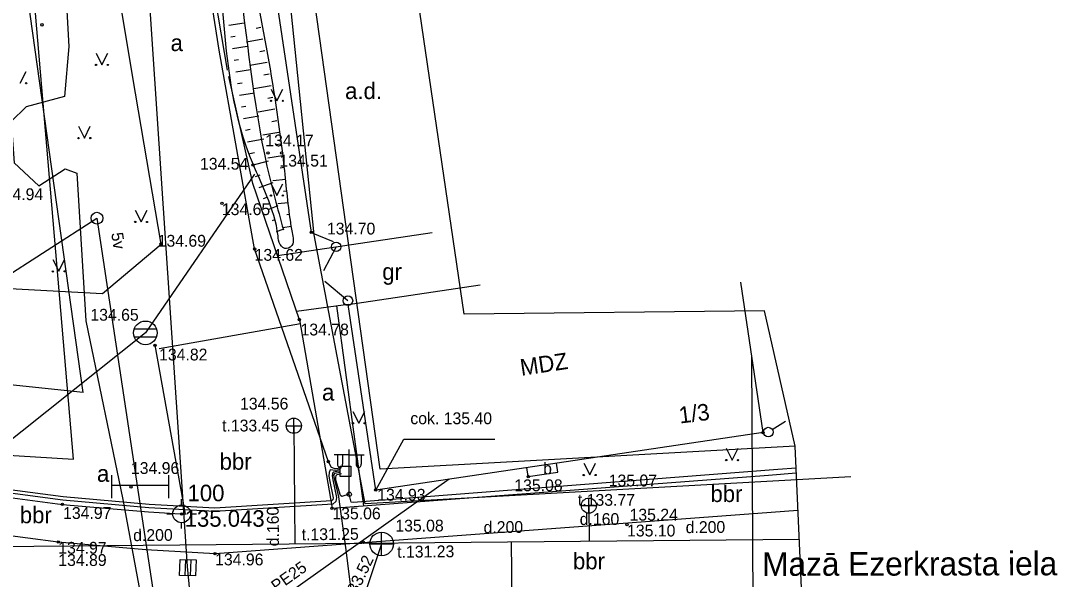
# Model space of a CAD drawing. Extents: x 728710 to 728960, y 272811 to 273475.
# Drawn here: x 728772.47 to 728816.33, y 273368.37 to 273391.98 of the extents above; entities that cross this region are included whole.
import ezdxf

# ---------------------------------------------------------------- set-up
doc = ezdxf.new("R2010")
doc.units = 0
for name, color, linetype in [('Level 10', 7, 'Continuous'), ('Level 12', 7, 'Continuous'), ('Level 15', 7, 'Continuous'), ('Level 17', 7, 'Continuous'), ('Level 18', 7, 'Continuous'), ('Level 19', 7, 'Continuous'), ('Level 21', 7, 'Continuous'), ('Level 23', 7, 'Continuous'), ('Level 25', 7, 'Continuous'), ('Level 26', 7, 'Continuous'), ('Level 28', 7, 'Continuous'), ('Level 29', 7, 'Continuous'), ('Level 3', 7, 'Continuous'), ('Level 34', 7, 'Continuous'), ('Level 38', 7, 'Continuous'), ('Level 4', 7, 'Continuous'), ('Level 40', 7, 'Continuous'), ('Level 42', 7, 'Continuous'), ('Level 43', 7, 'Continuous'), ('Level 48', 7, 'Continuous'), ('Level 50', 7, 'Continuous'), ('Level 53', 7, 'Continuous'), ('Level 54', 7, 'Continuous'), ('Level 55', 7, 'Continuous'), ('Level 56', 7, 'Continuous'), ('Level 57', 7, 'Continuous'), ('Level 58', 7, 'Continuous'), ('Level 59', 7, 'Continuous'), ('Level 60', 7, 'Continuous'), ('Level 62', 7, 'Continuous'), ('Level 63', 7, 'Continuous'), ('Level 9', 7, 'Continuous'), ('RAMI_UZMR_####_####_#', 7, 'Continuous'), ('ROBZ_ELEM_####_####_#', 7, 'Continuous'), ('ROBZ_PROJ_####_####_#', 7, 'Continuous'), ('ROBZ_UZMR_####_####_#', 7, 'Continuous'), ('TERT_KOKR_####_####_#', 7, 'Continuous'), ('TERT_KONT_####_####_#', 7, 'Continuous')]:
    doc.layers.add(name, color=color, linetype=linetype)

msp = doc.modelspace()

# ---------------------------------------------------------------- linework, layer by layer
at = {"layer": 'Level 10'}
for p, q in [((728779.278, 273371.512), (728779.278, 273371.762)), ((728778.653, 273371.137), (728778.903, 273371.137)), ((728779.278, 273370.512), (728779.278, 273370.762)), ((728779.653, 273371.137), (728779.903, 273371.137))]:
    msp.add_line(p, q, dxfattribs=at)
for radius in [0.375, 0.05]:
    msp.add_circle((728779.278, 273371.137), radius, dxfattribs=at)
at = {"layer": 'Level 12'}
for p, q in [((728781.28, 273391.804), (728781.919, 273391.896)), ((728782.634, 273391.693), (728782.432, 273391.658)), ((728781.352, 273391.309), (728781.541, 273391.337)), ((728782.719, 273391.2), (728782.027, 273391.081)), ((728781.424, 273390.814), (728782.051, 273390.906)), ((728782.804, 273390.708), (728782.592, 273390.671)), ((728781.497, 273390.32), (728781.684, 273390.348)), ((728782.89, 273390.215), (728782.169, 273390.09)), ((728781.571, 273389.825), (728782.195, 273389.92)), ((728782.975, 273389.722), (728782.756, 273389.685)), ((728781.647, 273389.331), (728781.835, 273389.36)), ((728783.059, 273389.229), (728782.327, 273389.105)), ((728781.725, 273388.837), (728782.357, 273388.938)), ((728783.142, 273388.736), (728782.924, 273388.7)), ((728781.806, 273388.344), (728781.998, 273388.375)), ((728781.889, 273387.851), (728782.543, 273387.962)), ((728783.225, 273388.243), (728782.51, 273388.124)), ((728783.306, 273387.75), (728783.098, 273387.716)), ((728781.974, 273387.358), (728782.176, 273387.394)), ((728782.064, 273386.866), (728782.749, 273386.994)), ((728783.386, 273387.256), (728782.716, 273387.148)), ((728783.465, 273386.762), (728783.272, 273386.732)), ((728782.157, 273386.375), (728782.366, 273386.415)), ((728783.542, 273386.268), (728782.927, 273386.174)), ((728782.261, 273385.886), (728782.952, 273386.062)), ((728783.616, 273385.774), (728783.441, 273385.75)), ((728782.399, 273385.405), (728782.594, 273385.468)), ((728783.679, 273385.278), (728783.136, 273385.214)), ((728782.563, 273384.933), (728783.15, 273385.152)), ((728783.734, 273384.781), (728783.586, 273384.766)), ((728782.744, 273384.467), (728782.897, 273384.528)), ((728782.932, 273384.004), (728783.36, 273384.177)), ((728783.785, 273384.284), (728783.347, 273384.238)), ((728783.118, 273383.54), (728783.223, 273383.58)), ((728783.84, 273383.787), (728783.724, 273383.773)), ((728783.293, 273383.071), (728783.575, 273383.17)), ((728783.905, 273383.291), (728783.562, 273383.233)), ((728783.416, 273382.588), (728783.416, 273382.588)), ((728783.994, 273382.799), (728783.994, 273382.799)), ((728783.807, 273382.38), (728783.807, 273382.381))]:
    msp.add_line(p, q, dxfattribs=at)
msp.add_spline([(728781.578, 273417.978), (728780.943, 273413.169), (728780.822, 273403.542), (728781.949, 273395.724), (728783.589, 273385.96), (728783.878, 273383.473), (728783.979, 273382.874), (728783.979, 273382.553), (728783.717, 273382.35), (728783.447, 273382.528), (728783.355, 273382.891), (728782.193, 273386.189), (728780.645, 273395.989), (728779.246, 273403.69), (728779.989, 273412.965), (728780.695, 273417.894)], degree=3, dxfattribs=at)
at = {"layer": 'Level 15'}
msp.add_circle((728775.694, 273383.637), 0.25, dxfattribs=at)
at = {"layer": 'Level 17'}
msp.add_line((728790.602, 273372.604), (728781.127, 273365.888), dxfattribs=at)
at = {"layer": 'Level 18'}
for p, q in [((728782.361, 273385.497), (728777.745, 273378.79)), ((728777.745, 273378.79), (728760.582, 273365.124))]:
    msp.add_line(p, q, dxfattribs=at)
for points in [[(728779.523, 273368.911), (728776.197, 273418.56)], [(728780.99, 273353.695), (728779.523, 273368.911)]]:
    msp.add_lwpolyline(points, dxfattribs=at)
at = {"layer": 'Level 21'}
for p, q in [((728763.288, 273375.684), (728775.694, 273383.637)), ((728775.694, 273383.637), (728780.859, 273349.374))]:
    msp.add_line(p, q, dxfattribs=at)
at = {"layer": 'Level 23'}
for p, q in [((728784.022, 273374.863), (728784.068, 273369.87)), ((728796.509, 273371.486), (728796.523, 273369.985)), ((728767.599, 273369.717), (728805.41, 273370.068)), ((728787.739, 273369.866), (728785.477, 273363.156)), ((728793.293, 273364.348), (728793.241, 273369.955))]:
    msp.add_line(p, q, dxfattribs=at)
at = {"layer": 'Level 25'}
for points in [[(728786.021, 273373.071), (728785.768, 273373.044), (728785.616, 273373.092), (728785.488, 273373.338), (728782.365, 273382.337), (728780.872, 273390.743), (728779.255, 273401.013)], [(728786.002, 273373.007), (728785.781, 273372.977), (728785.555, 273373), (728785.522, 273372.892), (728785.51, 273372.736), (728785.536, 273372.57), (728785.684, 273371.822), (728785.672, 273371.733), (728785.619, 273371.691), (728780.679, 273371.377), (728777.898, 273371.536), (728774.268, 273371.854), (728756.308, 273374.215), (728748.126, 273375.149), (728746.387, 273375.649), (728746.387, 273375.794), (728746.374, 273376.209), (728746.26, 273375.684), (728746.005, 273375.707)], [(728785.99, 273372.939), (728785.838, 273372.922), (728785.697, 273372.9), (728785.665, 273372.858), (728785.649, 273372.748), (728785.68, 273372.573), (728785.827, 273371.826), (728785.804, 273371.657), (728785.672, 273371.552), (728780.68, 273371.236), (728777.888, 273371.394), (728774.252, 273371.714), (728756.242, 273374.109), (728748.101, 273375.06), (728746.367, 273375.502), (728746.013, 273375.53)], [(728805.276, 273373.073), (728804.498, 273373.012), (728786.528, 273371.621), (728786.453, 273371.635), (728786.37, 273371.969), (728786.062, 273371.873), (728785.994, 273371.915), (728785.803, 273372.559), (728785.801, 273372.671), (728785.814, 273372.754), (728785.863, 273372.8), (728786.041, 273372.843)], [(728785.99, 273372.886), (728785.832, 273372.861), (728785.75, 273372.839), (728785.702, 273372.779), (728785.739, 273372.573), (728785.909, 273371.858), (728786.217, 273369.716), (728787.857, 273356.655), (728789.858, 273344.74), (728792.105, 273330.272), (728794.886, 273311.104), (728800.258, 273275.541), (728800.246, 273275.285), (728800.191, 273275.06), (728800.047, 273274.884), (728788.271, 273273.105), (728788.2, 273273.054), (728788.171, 273272.955), (728788.447, 273271.634)]]:
    msp.add_lwpolyline(points, dxfattribs=at)
at = {"layer": 'Level 26'}
for p, q in [((728786.371, 273371.97), (728786.371, 273373.853)), ((728786.371, 273373.637), (728785.736, 273373.632)), ((728785.871, 273373.633), (728785.871, 273373.241)), ((728786.081, 273373.635), (728786.081, 273373.241)), ((728786.371, 273373.637), (728787.006, 273373.632)), ((728786.661, 273373.635), (728786.661, 273373.241)), ((728786.871, 273373.633), (728786.871, 273373.241))]:
    msp.add_line(p, q, dxfattribs=at)
msp.add_lwpolyline([(728786.437, 273372.719), (728785.99, 273372.719), (728785.99, 273373.159), (728786.437, 273373.159)], close=True, dxfattribs=at)
msp.add_circle((728786.371, 273371.97), 0.09, dxfattribs=at)
for centre, major_axis, start_param, end_param in [((728785.976, 273373.241), (0, 0.151), 1.570796, 4.712389), ((728786.766, 273373.241), (0, -0.151), 4.712389, 7.853982)]:
    msp.add_ellipse(centre, major_axis=major_axis, ratio=0.695971, start_param=start_param, end_param=end_param, dxfattribs=at)
at = {"layer": 'Level 28'}
msp.add_lwpolyline([(728781.258, 273406.444), (728784.764, 273383.035), (728785.687, 273382.659)], dxfattribs=at)
at = {"layer": 'Level 29'}
for p, q in [((728784.022, 273374.543), (728784.022, 273375.183)), ((728783.702, 273374.863), (728784.342, 273374.863)), ((728796.509, 273371.166), (728796.509, 273371.806)), ((728796.189, 273371.486), (728796.829, 273371.486)), ((728787.739, 273369.366), (728787.739, 273370.366)), ((728787.239, 273369.866), (728788.239, 273369.866))]:
    msp.add_line(p, q, dxfattribs=at)
for centre, radius in [((728784.022, 273374.863), 0.32), ((728796.509, 273371.486), 0.32), ((728787.739, 273369.866), 0.5)]:
    msp.add_circle(centre, radius, dxfattribs=at)
at = {"layer": 'Level 3'}
for p, q in [((728803.879, 273374.575), (728802.935, 273380.939)), ((728786.322, 273379.995), (728791.914, 273380.826)), ((728787.488, 273372.141), (728786.322, 273379.995)), ((728803.879, 273374.575), (728787.488, 273372.141))]:
    msp.add_line(p, q, dxfattribs=at)
at = {"layer": 'Level 34'}
msp.add_spline([(728781.172, 273417.937), (728780.8, 273415.225), (728779.913, 273408.639), (728779.913, 273406.196), (728780.192, 273403.172), (728781.656, 273394.054), (728782.888, 273385.843), (728783.581, 273383.144)], degree=3, dxfattribs=at)
at = {"layer": 'Level 38'}
for p, q in [((728748.042, 273373.407), (728774.058, 273369.952)), ((728780.694, 273369.46), (728804.228, 273371.21)), ((728774.058, 273369.952), (728777.76, 273369.627)), ((728777.76, 273369.627), (728780.694, 273369.46))]:
    msp.add_line(p, q, dxfattribs=at)
at = {"layer": 'Level 4'}
for p, q in [((728781.219, 273389.895), (728777.803, 273410.117)), ((728777.326, 273388.924), (728773.859, 273409.451)), ((728782.293, 273385.101), (728781.268, 273389.633)), ((728778.409, 273382.543), (728777.326, 273388.924)), ((728784.262, 273379.343), (728782.293, 273385.101)), ((728783.334, 273382.058), (728789.872, 273383.028)), ((728775.929, 273380.456), (728778.409, 273382.543)), ((728767.98, 273380.871), (728775.929, 273380.456)), ((728784.262, 273379.343), (728785.641, 273371.372)), ((728779.446, 273371.128), (728778.156, 273378.263)), ((728748.223, 273374.991), (728774.233, 273371.537)), ((728785.641, 273371.372), (728804.102, 273372.779)), ((728804.102, 273372.779), (728805.285, 273372.869)), ((728774.233, 273371.537), (728777.875, 273371.217)), ((728777.875, 273371.217), (728779.446, 273371.128)), ((728804.228, 273371.21), (728805.355, 273371.293))]:
    msp.add_line(p, q, dxfattribs=at)
for points in [[(728786.322, 273379.995), (728784.144, 273379.689)], [(728786.98, 273371.474), (728785.849, 273379.929)], [(728778.324, 273378.122), (728784.308, 273379.18)]]:
    msp.add_lwpolyline(points, dxfattribs=at)
at = {"layer": 'Level 40'}
for p, q in [((728777.277, 273378.965), (728778.213, 273378.965)), ((728777.277, 273378.615), (728778.213, 273378.615)), ((728779.436, 273369.204), (728779.412, 273368.53)), ((728779.661, 273369.196), (728779.637, 273368.522))]:
    msp.add_line(p, q, dxfattribs=at)
msp.add_lwpolyline([(728779.211, 273369.213), (728779.886, 273369.188), (728779.861, 273368.514), (728779.187, 273368.538)], close=True, dxfattribs=at)
msp.add_circle((728777.745, 273378.79), 0.5, dxfattribs=at)
at = {"layer": 'Level 42'}
msp.add_lwpolyline([(728744.127, 273417.336), (728753.529, 273417.32), (728763.941, 273415.674), (728771.995, 273414.301), (728772.789, 273413.658), (728772.866, 273409.228), (728774.333, 273393.944), (728774.498, 273390.902), (728774.316, 273388.778), (728772.706, 273388.348), (728772.062, 273387.726), (728772.188, 273385.974), (728773.233, 273385.001), (728774.349, 273385.73), (728774.847, 273385.541), (728775.23, 273379.296), (728776.795, 273371.75), (728778.361, 273363.303)], dxfattribs=at)
at = {"layer": 'Level 43'}
for p, q in [((728785.814, 273382.426), (728785.273, 273381.418)), ((728786.313, 273380.15), (728785.334, 273380.962)), ((728804.269, 273374.702), (728804.829, 273375.062))]:
    msp.add_line(p, q, dxfattribs=at)
for centre in [(728785.814, 273382.426), (728786.313, 273380.15), (728804.101, 273374.594)]:
    msp.add_circle(centre, 0.202, dxfattribs=at)
at = {"layer": 'Level 48'}
for centre, radius in [((728773.369, 273391.811), 0.0534), ((728782.927, 273386.397), 0.05), ((728783.516, 273386.397), 0.05), ((728782.292, 273385.885), 0.05), ((728780.979, 273384.267), 0.05), ((728784.764, 273383.035), 0.05), ((728778.409, 273382.543), 0.05), ((728782.365, 273382.337), 0.05), ((728784.262, 273379.343), 0.05), ((728778.156, 273378.263), 0.05), ((728803.879, 273374.575), 0.05), ((728785.488, 273373.338), 0.05), ((728793.946, 273372.717), 0.05), ((728777.132, 273372.278), 0.05), ((728787.488, 273372.141), 0.05), ((728774.233, 273371.537), 0.05), ((728779.278, 273371.137), 0.05), ((728785.641, 273371.372), 0.05), ((728798.124, 273370.682), 0.05), ((728774.058, 273369.952), 0.05), ((728786.966, 273369.928), 0.05), ((728780.694, 273369.46), 0.05)]:
    msp.add_circle(centre, radius, dxfattribs=at)
at = {"layer": 'Level 9'}
for p, q in [((728793.946, 273372.717), (728793.89, 273373.092)), ((728795.2, 273372.903), (728795.144, 273373.278)), ((728793.946, 273372.717), (728795.2, 273372.903))]:
    msp.add_line(p, q, dxfattribs=at)
msp.add_lwpolyline([(728787.488, 273372.141), (728788.684, 273374.299), (728792.536, 273374.299)], dxfattribs=at)
at = {"layer": 'RAMI_UZMR_####_####_#'}
msp.add_line((728803.474, 273364.481), (728803.407, 273377.757), dxfattribs=at)
msp.add_lwpolyline([(728810.773, 273260.978), (728802.611, 273315.901), (728795.796, 273348.362), (728794.274, 273357.438), (728805.771, 273362.009), (728805.234, 273373.998), (728803.936, 273379.727), (728791.234, 273379.578), (728787.734, 273403.429), (728803.558, 273404.599), (728803.908, 273418.239), (728787.419, 273421.679), (728754.475, 273424.404), (728743.982, 273420.563), (728745.23, 273392.888), (728745.879, 273378.489), (728747.149, 273361.103), (728773.116, 273356.557), (728775.22, 273317.659), (728767.872, 273315.668), (728768.286, 273308.258), (728775.846, 273306.093), (728776.746, 273299.712), (728774.767, 273288.109)], dxfattribs=at)
at = {"layer": 'ROBZ_ELEM_####_####_#'}
for points in [[(728775.108, 273376.265), (728772.453, 273395.191), (728770.82, 273416.523)], [(728787.679, 273373.026), (728784.39, 273396.483), (728782.92, 273415.669)], [(728775.108, 273376.265), (728746.939, 273379.224)], [(728805.234, 273373.998), (728787.679, 273373.026)]]:
    msp.add_lwpolyline(points, dxfattribs=at)
at = {"layer": 'ROBZ_PROJ_####_####_#'}
for points in [[(728776.308, 273372.771), (728776.308, 273371.808)], [(728778.716, 273372.771), (728778.716, 273371.808)], [(728776.308, 273372.351), (728778.716, 273372.351)]]:
    msp.add_lwpolyline(points, dxfattribs=at)
at = {"layer": 'ROBZ_UZMR_####_####_#'}
for p, q in [((728784.885, 273382.939), (728782.32, 273408.103)), ((728774.702, 273373.447), (728772.942, 273394.12)), ((728787.04, 273371.561), (728784.885, 273382.939)), ((728756.221, 273374.624), (728774.702, 273373.447)), ((728807.595, 273372.699), (728787.04, 273371.561))]:
    msp.add_line(p, q, dxfattribs=at)
at = {"layer": 'TERT_KONT_####_####_#'}
for p, q in [((728775.656, 273390.615), (728775.906, 273390.115)), ((728775.906, 273390.115), (728776.156, 273390.615)), ((728772.448, 273389.343), (728772.698, 273389.843)), ((728783.059, 273389.099), (728783.309, 273388.599)), ((728783.309, 273388.599), (728783.559, 273389.099)), ((728774.913, 273387.526), (728775.163, 273387.026)), ((728775.163, 273387.026), (728775.413, 273387.526)), ((728783.059, 273385.094), (728783.309, 273384.594)), ((728783.309, 273384.594), (728783.559, 273385.094)), ((728777.314, 273383.979), (728777.564, 273383.479)), ((728777.564, 273383.479), (728777.814, 273383.979)), ((728773.827, 273381.891), (728774.077, 273381.391)), ((728774.077, 273381.391), (728774.327, 273381.891)), ((728786.525, 273375.469), (728786.775, 273374.969)), ((728786.775, 273374.969), (728787.025, 273375.469)), ((728802.322, 273373.91), (728802.572, 273373.41)), ((728802.572, 273373.41), (728802.822, 273373.91)), ((728796.292, 273373.281), (728796.542, 273372.781)), ((728796.542, 273372.781), (728796.792, 273373.281))]:
    msp.add_line(p, q, dxfattribs=at)
for centre, radius in [((728775.656, 273390.114), 0.028), ((728776.156, 273390.114), 0.0263), ((728772.697, 273389.342), 0.0263), ((728783.058, 273388.598), 0.028), ((728783.558, 273388.598), 0.0263), ((728774.913, 273387.025), 0.028), ((728775.413, 273387.025), 0.0263), ((728783.058, 273384.594), 0.028), ((728783.558, 273384.594), 0.0263), ((728777.313, 273383.478), 0.028), ((728777.813, 273383.478), 0.0263), ((728773.827, 273381.39), 0.028), ((728774.327, 273381.39), 0.0263), ((728786.525, 273374.969), 0.028), ((728787.025, 273374.969), 0.0263), ((728802.322, 273373.41), 0.028), ((728802.822, 273373.41), 0.0263), ((728796.291, 273372.78), 0.028), ((728796.791, 273372.78), 0.0263)]:
    msp.add_circle(centre, radius, dxfattribs=at)

# ---------------------------------------------------------------- texts
at = {"layer": 'Level 19'}
msp.add_text(' 134.65', height=0.5, dxfattribs=at).set_placement((728775.23, 273379.304))
at = {"layer": 'Level 50'}
for s, p in [('cok. 135.40', (728788.954, 273374.928)), ('b', (728794.573, 273372.81))]:
    msp.add_text(s, height=0.5, dxfattribs=at).set_placement(p)
at = {"layer": 'Level 53'}
msp.add_text('5v', height=0.5, rotation=278.683, dxfattribs=at).set_placement((728776.296, 273382.999))
at = {"layer": 'Level 54'}
msp.add_text('Mazā Ezerkrasta iela', height=1, rotation=0.1163, dxfattribs=at).set_placement((728803.841, 273368.515))
at = {"layer": 'Level 55'}
msp.add_text('PE25', height=0.5, rotation=35.329, dxfattribs=at).set_placement((728783.29, 273367.817))
at = {"layer": 'Level 56'}
for s, p in [('134.56', (728781.748, 273375.549)), ('135.07', (728797.347, 273372.298)), ('135.08', (728788.32, 273370.392))]:
    msp.add_text(s, height=0.5, dxfattribs=at).set_placement(p)
at = {"layer": 'Level 57'}
for s, p in [('134.17', (728782.817, 273386.672)), ('134.54', (728780.053, 273385.689)), ('134.51', (728783.416, 273385.82)), (' 134.94', (728771.189, 273384.4)), ('134.65', (728780.979, 273383.767)), (' 134.70', (728785.241, 273382.948)), ('134.69', (728778.263, 273382.432)), ('134.62', (728782.365, 273381.837)), ('134.78', (728784.308, 273378.68)), ('134.82', (728778.324, 273377.622)), ('134.96', (728777.132, 273372.825)), (' 135.08', (728793.167, 273372.094)), ('134.93', (728787.554, 273371.694)), ('134.97', (728774.262, 273370.922)), ('135.06', (728785.655, 273370.906)), ('135.24', (728798.229, 273370.853)), ('135.10', (728798.124, 273370.182)), ('134.97', (728774.058, 273369.452)), ('134.89', (728774.058, 273368.935)), ('134.96', (728780.694, 273368.96))]:
    msp.add_text(s, height=0.5, dxfattribs=at).set_placement(p)
at = {"layer": 'Level 58'}
for s, p in [('a', (728778.809, 273390.701)), ('gr', (728787.766, 273381.029)), ('a', (728785.216, 273375.93)), ('bbr', (728780.885, 273373.003)), ('a', (728775.694, 273372.493)), ('bbr', (728801.653, 273371.637)), ('bbr', (728772.43, 273370.741)), ('bbr', (728795.836, 273368.794))]:
    msp.add_text(s, height=0.7, dxfattribs=at).set_placement(p)
at = {"layer": 'Level 59'}
msp.add_text('MDZ', height=0.7, rotation=8.445, dxfattribs=at).set_placement((728793.652, 273376.972))
at = {"layer": 'Level 60'}
for s, p in [('t.133.45', (728780.989, 273374.621)), ('t.133.77', (728796.044, 273371.479)), ('d.160', (728796.12, 273370.668))]:
    msp.add_text(s, height=0.5, dxfattribs=at).set_placement(p)
for s, rotation, p in [('d.160', 90.5313, (728783.397, 273369.769)), ('d.200', 0.5313, (728792.055, 273370.321)), ('d.200', 0.5313, (728800.606, 273370.321)), ('d.200', 0.5313, (728777.228, 273369.984)), ('t.131.25', 0.5313, (728784.357, 273370.019)), ('t.131.23', 0.5313, (728788.4, 273369.282)), ('t.133.52', 64.5762, (728786.382, 273367.048))]:
    msp.add_text(s, height=0.5, rotation=rotation, dxfattribs=at).set_placement(p)
at = {"layer": 'Level 62'}
msp.add_text('1/3', height=0.7, rotation=7.13, dxfattribs=at).set_placement((728800.36, 273374.955))
at = {"layer": 'Level 63'}
for s, p in [('100', (728779.527, 273371.67)), ('135.043', (728779.406, 273370.593))]:
    msp.add_text(s, height=0.7, dxfattribs=at).set_placement(p)
at = {"layer": 'TERT_KOKR_####_####_#'}
msp.add_text('a.d.', height=0.7, dxfattribs=at).set_placement((728786.193, 273388.672))

doc.saveas('drawing.dxf')
